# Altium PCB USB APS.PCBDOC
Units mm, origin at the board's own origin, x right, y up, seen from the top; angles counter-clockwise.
Board outline 152.4 x 101.6 mm, 2 copper layers (Top Layer, Bottom Layer); 23 components, 20 nets, 139 pads, 0 vias.
Unrouted connection lines stored in the file: 6.
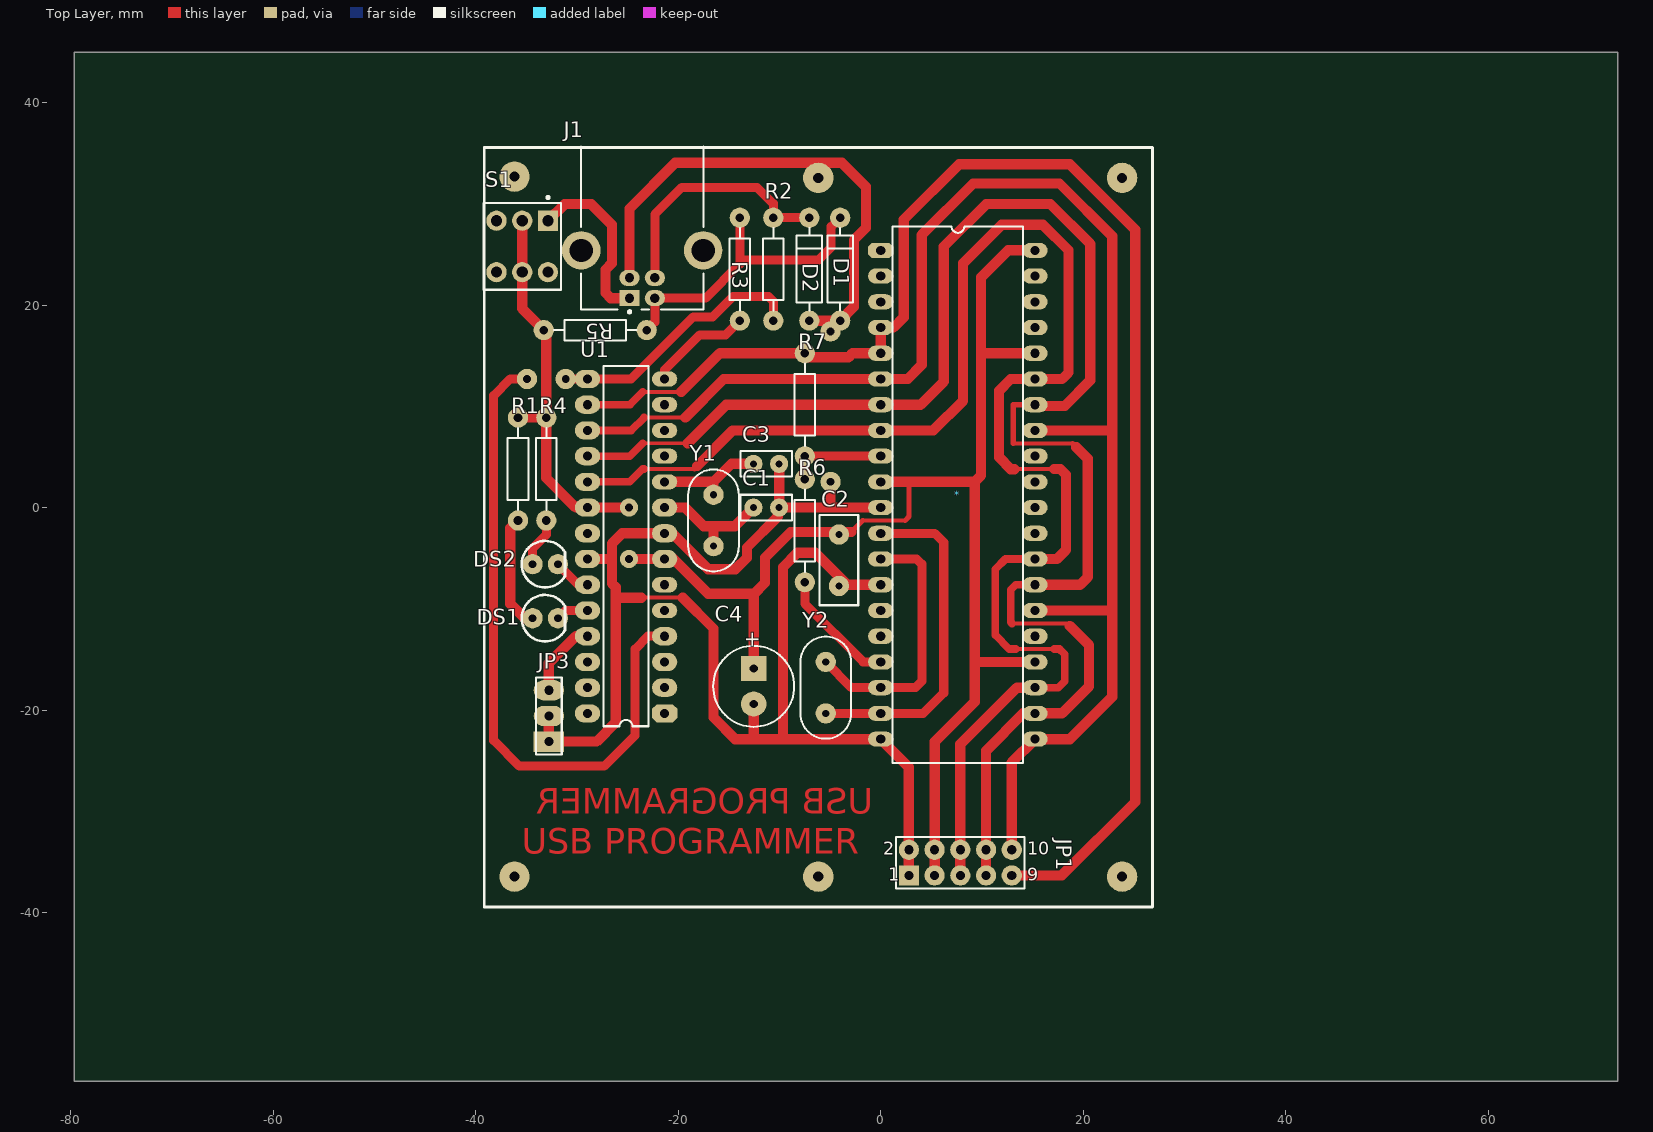
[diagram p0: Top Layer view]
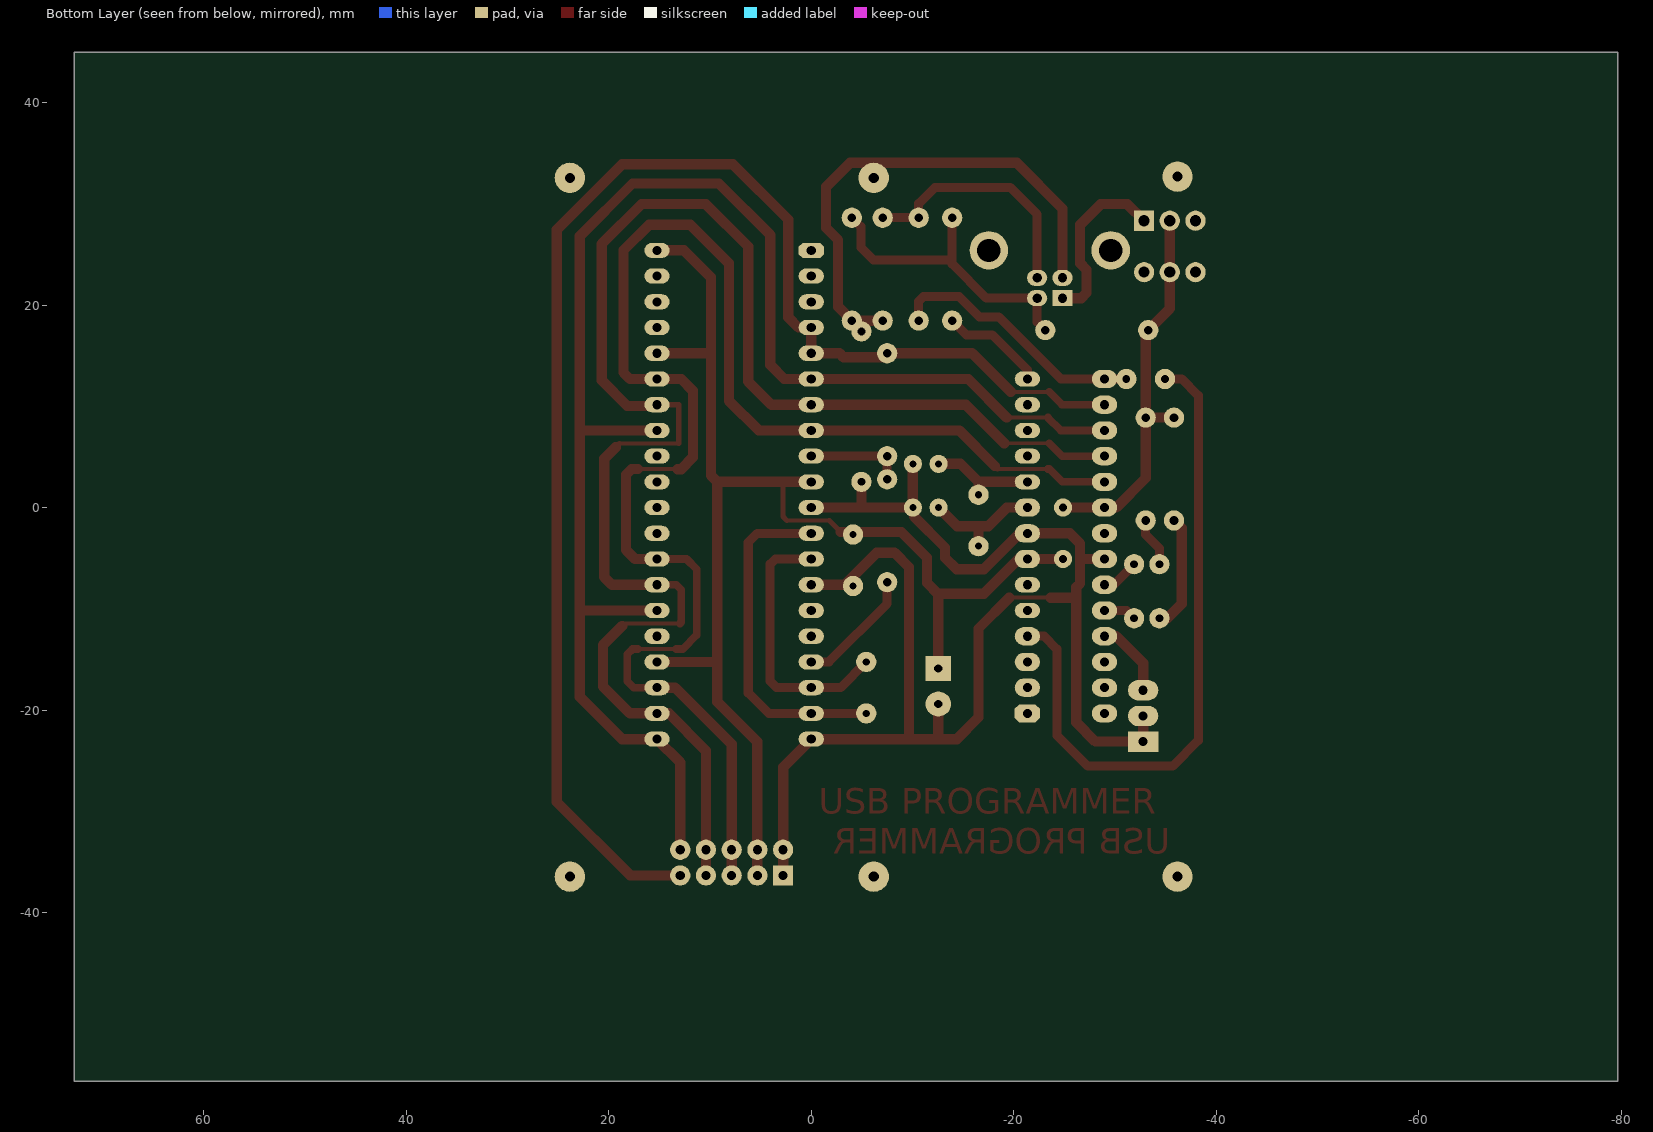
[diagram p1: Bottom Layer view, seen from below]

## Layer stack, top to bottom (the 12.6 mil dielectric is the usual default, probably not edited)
Top Layer: signal copper 0.0356
Dielectric: dielectric 0.32, FR-4, Dk 4.8
Bottom Layer: signal copper 0.0356

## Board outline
-79.629,-56.642 72.771,-56.642 72.771,44.958 -79.629,44.958

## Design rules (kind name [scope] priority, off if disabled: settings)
Clearance [All] p1: gap=0.254
PolygonConnect [All] p1: connectstyle=Relief reliefconductorwidth=0.254 reliefentries=4 polygonreliefangle="90 Angle"
RoutingVias [All] p1: holewidth=0.711 width=1.27 viastyle="Through Hole" minholewidth=0.711 minwidth=1.27 maxholewidth=0.711 maxwidth=1.27
SolderMaskExpansion [All] p1: expansion=0.102
TestPointUsage [All] p1: valid=0 allowmultiple=FALSE
Testpoint [All] p1: side=15 testpointundercomponent=TRUE minsize=1.016 maxsize=2.54 preferedsize=1.524 minholesize=0 maxholesize=1.016 preferedholesize=0.813 testpointgrid=0.025 style=1023 order=0-123456789
Width [All] p1: maxlimit=8 minlimit=0.254 preferedwidth=0.254 toplayer_prefwidth=1.016 minimp=50.000000 maximp=50.000000 favimp=50.000000
19 further rules are at their usual default settings.

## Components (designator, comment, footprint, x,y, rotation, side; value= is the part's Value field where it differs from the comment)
* "zif sucket" 40P6 7.62,1.27 r270 top
C1 "Cap" RAD-0.1 -11.303,0 r0 top
C2 "Cap" RAD-0.2 -4.125,-5.198 r90 top
C3 "Cap" RAD-0.1 -11.303,4.318 r0 top
C4 "Cap Pol1" CAPPR3.5-8x5 -12.541,-17.644 r270 top
D1 "D Zener" DIODE-0.4 -4.004,23.543 r90 top
D2 "D Zener" DIODE-0.4 -7.052,23.543 r90 top
DS1 "LED0" LED3mm -31.877,-10.922 r180 top
DS2 "LED0" LED3mm -31.877,-5.588 r180 top
J1 "1-1470156-1" 1-1470156 -23.556,35.696 r90 top
JP1 "Header 5X2" HDR2X5 2.781,-36.322 r0 top
JP3 "Header 3" HDR1X3 -32.766,-23.114 r90 top
R1 "Res1" AXIAL-0.4 -35.814,3.81 r270 top
R2 "Res1" AXIAL-0.4 -10.608,23.543 r270 top
R3 "Res1" AXIAL-0.4 -13.91,23.543 r270 top
R4 "Res1" AXIAL-0.4 -33.02,3.81 r270 top
R5 "Res1" AXIAL-0.4 -28.194,17.526 r180 top
R6 "Res1" AXIAL-0.4 -7.493,-2.286 r90 top
R7 "Res1" AXIAL-0.4 -7.493,10.16 r90 top
S1 "SW-DPDT" DPDT-6 -35.401,25.79 r270 top
U1 "ATmega8-16PC" 28P3 -25.146,-3.81 r90 top
Y1 "XTAL" "xtal - duplicate" -16.51,1.27 r270 top
Y2 "XTAL" "xtal - duplicate" -5.429,-20.32 r90 top

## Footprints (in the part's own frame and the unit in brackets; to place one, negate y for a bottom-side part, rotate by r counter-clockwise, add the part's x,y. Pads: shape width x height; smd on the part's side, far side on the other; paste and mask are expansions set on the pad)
1-1470156 [mm] "Connector; USB1.1, Type B, Thru-Hole; 4 Position; Right Angle"
  rect 1.6x2 hole 0.92: 1(-15.01,1.25)
  oval 1.6x2 hole 0.92: 2(-15.01,-1.25) 3(-13.01,-1.25) 4(-13.01,1.25)
  round 3.8 hole 2.3: 5(-10.3,6.02) 6(-10.3,-6.02)
  silkscreen extent -16.48,-6.05 -0.02,6.05
28P3 [mm] "DIP; 28 Leads; Row Spacing 7.62 mm; Pitch 2.54 mm"
  oct 1.8x2.5 hole 0.9: 1(-16.51,-3.81)
  oval 1.8x2.5 hole 0.9: 2(-13.97,-3.81) 3(-11.43,-3.81) 4(-8.89,-3.81) 7(-1.27,-3.81) 8(1.27,-3.81) 9(3.81,-3.81) 15(16.51,3.81) 16(13.97,3.81) 17(11.43,3.81) 18(8.89,3.81) 19(6.35,3.81) 20(3.81,3.81) 21(1.27,3.81) 22(-1.27,3.81) 23(-3.81,3.81) 24(-6.35,3.81) 25(-8.89,3.81) 26(-11.43,3.81) 27(-13.97,3.81) 28(-16.51,3.81)
  oval 1.5x2.5 hole 0.9: 5(-6.35,-3.81) 6(-3.81,-3.81) 10(6.35,-3.81) 11(8.89,-3.81) 12(11.43,-3.81) 13(13.97,-3.81) 14(16.51,-3.81)
  silkscreen extent -17.78,-2.23 17.78,2.23
40P6 [mm] "DIP; 40 Leads; Row Spacing 15.24 mm; Pitch 2.54 mm"
  oct 1.5x2.5 hole 0.9: 1(-24.13,-7.62)
  oval 1.5x2.5 hole 0.9: 2(-21.59,-7.62) 3(-19.05,-7.62) 4(-16.51,-7.62) 5(-13.97,-7.62) 6(-11.43,-7.62) 7(-8.89,-7.62) 8(-6.35,-7.62) 9(-3.81,-7.62) 10(-1.27,-7.62) 11(1.27,-7.62) 12(3.81,-7.62) 13(6.35,-7.62) 14(8.89,-7.62) 15(11.43,-7.62) 16(13.97,-7.62) 17(16.51,-7.62) 18(19.05,-7.62) 19(21.59,-7.62) 20(24.13,-7.62) 21(24.13,7.62) 22(21.59,7.62) 23(19.05,7.62) 24(16.51,7.62) 25(13.97,7.62) 26(11.43,7.62) 27(8.89,7.62) 28(6.35,7.62) 29(3.81,7.62) 30(1.27,7.62) 31(-1.27,7.62) 32(-3.81,7.62) 33(-6.35,7.62) 34(-8.89,7.62) 35(-11.43,7.62) 36(-13.97,7.62) 37(-16.51,7.62) 38(-19.05,7.62) 39(-21.59,7.62) 40(-24.13,7.62)
  silkscreen extent -26.5,-6.45 26.5,6.45
AXIAL-0.4 [mm] "Resistor; 2 Leads"
  round 2 hole 0.85: 1(-5.08,0) 2(5.08,0)
  silkscreen extent -4.06,-1.02 4.06,1.02
CAPPR3.5-8x5 [mm]
  rect 2.5x2.5 hole 0.8: 1(-1.75,0)
  round 2.5 hole 0.8: 2(1.75,0)
  silkscreen extent -4,-4 4,4
DIODE-0.4 [mm]
  round 2 hole 0.85: 1(-5.08,0) 2(5.08,0)
  silkscreen extent -4.06,-1.27 4.06,1.27
DPDT-6 [mm] "Double-Pole, Double-Throw Switch; 6 Leads"
  rect 2x2 hole 1.1: 1(-2.54,2.54)
  round 2 hole 1.1: 2(-2.54,0) 3(-2.54,-2.54) 4(2.54,-2.54) 5(2.54,0) 6(2.54,2.54)
  silkscreen extent -4.96,-3.81 4.28,3.81
HDR1X3 [mm] "Connector; Header; 3 Position"
  rect 2x3 hole 0.9: 1(0,0)
  oval 2x3 hole 0.9: 2(2.54,0) 3(5.08,0)
  silkscreen extent -1.27,-1.27 6.35,1.27
HDR2X5 [mm] "Connector; Header; 5x2 Position"
  rect 2x2 hole 0.9: 1(0,0)
  round 2 hole 0.9: 2(0,2.54) 3(2.54,0) 4(2.54,2.54) 5(5.08,0) 6(5.08,2.54) 7(7.62,0) 8(7.62,2.54) 9(10.16,0) 10(10.16,2.54)
  silkscreen extent -1.27,-1.27 11.43,3.81
LED3mm [mm]
  round 2 hole 0.762: 1(2.5,0) 2(0,0)
  silkscreen extent -0.7,-2.3 3.57,2.3
RAD-0.1 [mm]
  round 1.8 hole 0.7: 1(-1.27,0) 2(1.27,0)
  silkscreen extent -2.54,-1.27 2.54,1.27
RAD-0.2 [mm]
  round 2 hole 0.7: 1(-2.54,0) 2(2.54,0)
  silkscreen extent -4.44,-1.91 4.44,1.91
"xtal - duplicate" [mm]
  round 2 hole 0.7: 1(0,0) 2(5.08,0)
  silkscreen extent -2.5,-2.5 7.58,2.5

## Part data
*: library part Component_1
C1 C2 C3: "Capacitor"
C4: "Polarized Capacitor (Radial)"
D1 D2: "Zener Diode"
DS1 DS2: "Typical INFRARED GaAs LED"
J1: "USB 1.1, Right Angle, Thru-Hole, B Type, Receptacle, 4 Position, White"
JP1: "Header, 5-Pin, Dual row"
JP3: "Header, 3-Pin"
R1 R2 R3 R4 R5 R6 R7: "Resistor"
S1: "Double-Pole, Double-Throw Switch"
U1: "8-Bit AVR Microcontroller with 8K Bytes of In-System Programmable Flash Memory"
Y1 Y2: "Crystal Oscillator"

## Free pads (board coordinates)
  round 3 hole 1: 0(-36.163,-36.44) 0(-36.163,32.687) 0(-6.163,-36.44) 0(-6.163,32.56) 0(23.837,-36.44) 0(23.837,32.56)
  round 2 hole 0.762: 0(-34.925,12.7) 2(-31.115,12.7) 7(-4.953,17.399) 8(-4.953,2.54)
  round 1.8 hole 0.762: 0(-24.86,-5.071) 1(-24.86,0.009)

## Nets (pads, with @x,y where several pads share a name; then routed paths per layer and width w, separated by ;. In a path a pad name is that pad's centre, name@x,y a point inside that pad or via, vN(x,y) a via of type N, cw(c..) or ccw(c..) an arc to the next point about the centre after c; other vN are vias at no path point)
GND: *.11 *.14 *.20 C1.2 C2.1 C3.2 C4.2 D1.1 D2.1 J1.4 JP1.1 JP1.2 JP3.1 JP3.2 pad.0@-6.163,32.56 pad.7 pad.8 U1.8 U1.22 | length 203
  Top Layer w0.381: -23.622,-8.89 -19.558,-8.89
  Top Layer w1.016: JP3.2 JP3.1 ; U1.22 -26.67,-5.08 -26.543,-5.207 ; J1.4 -24.806,29.527 -20.288,34.045 -3.838,34.045 -1.464,31.671 -1.464,27.607 -2.648,26.423 -2.648,19.819 D1.1 D2.1 ; -23.622,-8.89 -26.162,-8.89 ; U1.8@-21.59,-2.794 -21.844,-2.54 -25.527,-2.54 -26.543,-3.556 -26.543,-5.207 ; U1.8 -20.574,-2.54 -17.018,-6.096 -14.351,-6.096 -13.208,-4.953 -13.208,-3.937 -10.16,-0.889 -10.16,0 C1.2 ; -19.558,-8.89 -16.51,-11.938 -16.51,-20.701 -14.351,-22.86 -9.652,-22.86 ; -12.541,-22.828 C4.2 ; C3.2 C1.2 ; pad.8 -4.953,0 ; *.14 -3.302,-7.62 -6.477,-4.445 -8.223,-4.445 -9.652,-5.874 -9.652,-22.86 ; *.11 -4.953,0 ; JP1.1 JP1.2 2.781,-25.641 *.20 -9.652,-22.86 ; JP3.1 JP3.1@-32.757,-23.105 ; JP3.1 JP3.1@-32.757,-23.105 ; JP3.1@-32.757,-23.105 -28.058,-23.105 -26.162,-21.209 -26.162,-8.89 ; -26.543,-5.207 -26.543,-7.493 -26.162,-7.874 -26.162,-8.89 ; C1.2 -4.953,0
Net*_4: *.4 *.5 *.9 *.17 JP1.9 R6.1 R6.2 R7.1 R7.2 U1.16 | length 167.6
  Top Layer w0.381: -23.495,11.43 -19.685,11.43
  Top Layer w0.762: U1.16 -24.765,10.16 -23.495,11.43
  Top Layer w0.889: R6.1 -7.493,-9.484 -1.737,-15.24 *.17 ; R6.2 R7.1 *.9
  Top Layer w1.016: -19.685,11.43 -15.875,15.24 R7.2 -7.112,14.859 -3.175,14.859 -2.794,15.24 *.5 *.4 1.27,17.78 2.286,18.796 2.286,28.448 7.747,33.909 18.669,33.909 25.146,27.432 25.146,-29.07 17.894,-36.322 JP1.9
Net*_6: *.6 *.21 *.26 *.33 JP1.10 U1.17 | length 156.8
  Top Layer w0.254: *.26 18.415,-10.16
  Top Layer w0.381: -23.368,8.89 -19.304,8.89
  Top Layer w0.508: U1.17@-29.083,7.62 U1.17
  Top Layer w0.762: U1.17 -24.638,7.62 -23.368,8.89
  Top Layer w1.016: -19.304,8.89 -15.494,12.7 *.6 2.667,12.7 4.064,14.097 4.064,26.924 9.144,32.004 17.653,32.004 22.86,26.797 22.86,7.62 ; JP1.10 12.941,-25.159 *.21 18.669,-22.86 22.86,-18.669 22.86,-10.16 ; *.26 22.86,-10.16 ; *.33 22.86,7.62 ; 22.86,-10.16 22.86,7.62
Net*_7: *.7 *.22 *.27 *.34 JP1.7 JP1.8 U1.18 | length 165.1
  Top Layer w0.254: *.27 *.27@16.129,-7.62 ; *.34 *.34@15.367,10.16
  Top Layer w0.381: -23.495,6.359 -19.041,6.359 ; 12.966,-11.442 18.427,-11.442 18.669,-11.684 ; 13.093,6.338 18.935,6.338
  Top Layer w0.508: 13.093,6.338 13.081,6.35 13.081,10.16 *.34 ; 18.935,6.338 19.304,5.969
  Top Layer w0.762: U1.18 -24.774,5.08 -23.495,6.359 ; 12.966,-11.442 12.827,-11.303 12.827,-8.128 13.335,-7.62 *.27
  Top Layer w1.016: -19.041,6.359 -15.24,10.16 *.7 3.937,10.16 6.223,12.446 6.223,25.781 10.414,29.972 16.764,29.972 20.701,26.035 20.701,12.573 18.161,10.033 *.34@15.367,10.033 ; JP1.7 10.401,-24.003 14.084,-20.32 *.22 17.907,-20.32 20.574,-17.653 20.574,-13.589 18.669,-11.684 ; *.27 19.685,-7.62 20.447,-6.858 20.447,4.826 19.304,5.969
Net*_8: *.8 *.23 *.28 *.35 JP1.5 JP1.6 U1.19 | length 158.5
  Top Layer w0.381: -23.368,3.819 -18.406,3.819 ; 13.208,3.798 17.145,3.81 ; 13.335,-13.97 17.145,-13.97
  Top Layer w0.508: -18.406,3.819 -18.12,4.105
  Top Layer w0.762: U1.19 -24.774,2.54 -23.495,3.819 -23.368,3.819 ; 13.335,-13.97 12.7,-13.97 11.303,-12.573 11.303,-6.096 12.319,-5.08 *.28 ; *.23 17.526,-17.78 18.161,-17.145 18.161,-14.478 17.653,-13.97 17.145,-13.97
  Top Layer w1.016: -18.12,4.105 -14.605,7.62 *.8 5.207,7.62 8.128,10.541 8.128,24.13 11.938,27.94 16.002,27.94 18.542,25.4 18.542,13.335 17.907,12.7 *.35 12.827,12.7 11.684,11.557 11.684,4.953 12.839,3.798 13.208,3.798 ; JP1.5 JP1.6 7.861,-23.368 13.449,-17.78 *.23 ; *.28 17.399,-5.08 18.288,-4.191 18.288,3.267 17.745,3.81 17.145,3.81
NetD1_2: D1.2 J1.2 R3.1 R5.1 | length 30.7
  Top Layer w0.889: R5.1 -22.306,18.334 J1.2 -17.287,20.686 -13.91,24.063 -13.91,24.432 ; R3.1 -13.91,24.432 ; D1.2 -4.893,27.734 -4.893,25.702 -6.163,24.432 -13.91,24.432
NetD2_2: D2.2 J1.3 R2.1 | length 24.7
  Top Layer w0.889: J1.3 -22.306,28.951 -19.625,31.632 -12.22,31.632 -10.608,30.02 R2.1 D2.2
NetDS1_1: DS1.1 R1.2 | length 10.6
  Top Layer w1.016: R1.2 -36.576,-2.032 -36.576,-9.485 DS1.1@-35.139,-10.922
NetDS1_2: DS1.2 U1.24 | length 3.2
  Top Layer w0.889: DS1.2 -31.115,-10.16 U1.24
NetDS2_1: DS2.1 R4.2 | length 4.9
  Top Layer w0.889: DS2.1 -34.377,-4.024 -33.02,-2.667 R4.2
NetDS2_2: DS2.2 U1.23 | length 3.8
  Top Layer w0.889: DS2.2 -29.845,-7.62 U1.23
NetJ1_1: J1.1 S1.1 S1.4 | length 17.4
  Top Layer w1.016: S1.1 -31.219,29.972 -28.575,29.972 -26.543,27.94 -26.543,24.13 -27.178,23.495 -27.178,21.209 -26.655,20.686 J1.1
NetJP3_3: JP3.3 U1.25 | length 7.6
  Top Layer w1.016: JP3.3 -32.766,-15.367 -30.099,-12.7 U1.25
NetR2_2: pad.0@-34.925,12.7 pad.2 R2.2 U1.4 U1.15 | length 92.6
  Top Layer w0.889: pad.0@-34.544,12.7 -34.798,12.7 -36.576,12.7 -38.227,11.049 -38.227,-22.987 -35.687,-25.527 -27.305,-25.527 -24.257,-22.479 -24.257,-13.97 -22.987,-12.7 U1.4 ; pad.2 U1.15 -24.638,12.7 -18.494,18.844 -16.589,18.844 -14.605,20.828 -11.068,20.828 -10.608,20.368 R2.2
NetR3_2: R3.2 U1.14 | length 10.3
  Top Layer w0.889: U1.14 -21.336,13.589 -17.859,17.066 -15.307,17.066 R3.2
VCC: *.10 *.24 *.36 *.40 C2.2 C4.1 JP1.3 JP1.4 pad.0@-24.86,-5.071 pad.1 R1.1 R4.1 R5.2 S1.2 S1.5 U1.7 U1.20 | length 171.2
  Top Layer w0.381: -1.778,-1.27 2.413,-1.27
  Top Layer w0.508: -2.921,-2.413 -1.778,-1.27 ; 2.413,-1.27 2.794,-0.889 2.794,2.54
  Top Layer w1.016: R1.1 R4.1 ; S1.2 S1.5 -35.401,19.653 R5.2 -33.02,17.272 R4.1 ; R4.1@-32.893,8.89 R4.1 ; pad.0@-24.86,-5.071 -21.345,-5.071 U1.7 -20.447,-5.08 -17.018,-8.509 -12.509,-8.509 ; pad.1 -28.947,0.009 U1.20 -30.099,0 -33.02,2.921 R4.1 ; C4.1 -12.541,-8.541 -12.509,-8.509 ; -2.921,-2.413 -8.89,-2.413 -11.43,-4.953 -11.43,-7.43 -12.509,-8.509 ; *.10 2.794,2.54 9.271,2.54 ; JP1.3 JP1.4 5.321,-23.114 9.271,-19.164 9.271,2.54 ; 9.271,-15.24 *.24 ; *.36 9.906,15.24 ; *.40 12.573,25.4 9.906,22.733 9.906,15.24 ; 9.271,2.54 9.906,3.175 9.906,15.24
X1: C1.1 U1.9 Y1.2 | length 12.3
  Top Layer w1.016: U1.9 -19.304,0 -17.47,-1.834 -16.51,-1.834 ; Y1.2 -16.51,-1.834 ; C1.1 -14.407,-1.834 -16.51,-1.834
X2: C3.1 U1.10 Y1.1 | length 10.1
  Top Layer w1.016: U1.10 -16.51,2.54 ; Y1.1 -16.51,2.54 ; C3.1@-13.208,4.318 -14.732,4.318 -16.51,2.54
X21: *.12 *.19 Y2.1 | length 33.9
  Top Layer w0.889: Y2.1 *.19 4.191,-20.32 6.223,-18.288 6.223,-3.429 5.334,-2.54 *.12
X22: *.13 *.18 Y2.2 | length 26.6
  Top Layer w0.889: Y2.2 -2.889,-17.78 *.18 3.429,-17.78 4.064,-17.145 4.064,-5.588 3.556,-5.08 *.13
pads on no net: *.1 *.2 *.3 *.15 *.16 *.25 *.29 *.30 *.31 *.32 *.37 *.38 *.39 J1.5 J1.6 S1.3 S1.6 U1.1 U1.2 U1.3 U1.5 U1.6 U1.11 U1.12 U1.13 U1.21 U1.26 U1.27 U1.28

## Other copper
Top Layer:
  text "USB PROGRAMMER" at -0.762,-30.226 h2.54
  text "USB PROGRAMMER" at -35.464,-34.163 h2.54

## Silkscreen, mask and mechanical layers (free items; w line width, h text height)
Top Overlay:
  lines w0.254: -39.163,-39.44 -39.163,15.376 ; -39.163,15.139 -39.163,35.56 26.837,35.56 26.837,-39.44 -39.116,-39.44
